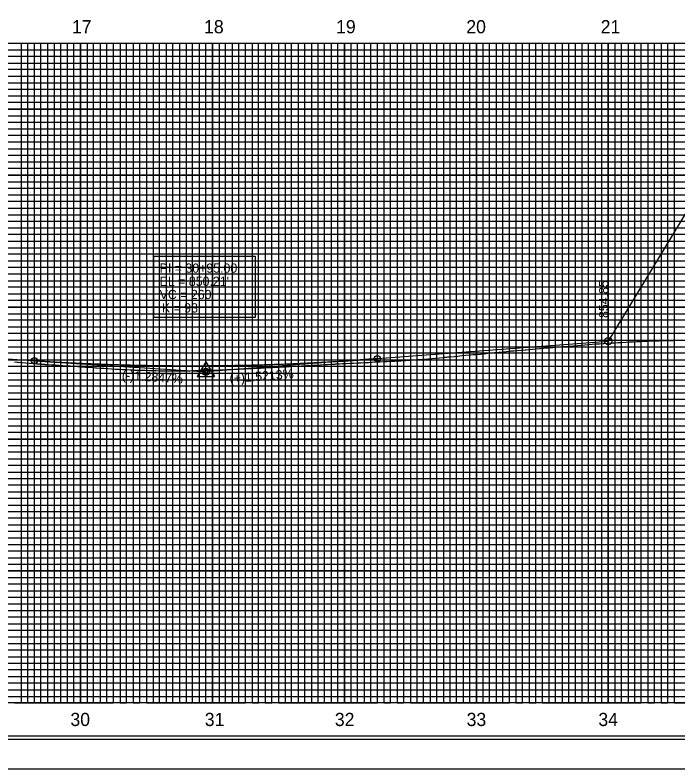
# Model space of a CAD drawing. Extents: x 570622 to 580296, y -55533 to -48575.
# Drawn here: x 571339 to 571841, y -53332 to -52761 of the extents above; entities that cross this region are included whole.
import ezdxf

# ---------------------------------------------------------------- set-up
doc = ezdxf.new("R2010")
doc.units = 0
for name, color, linetype in [('Exist Vertical Profile Ground Line', 7, 'Continuous'), ('Exist Vertical Profile Horizontal Axis Label Major', 7, 'Continuous'), ('Prop Grid Mask', 7, 'Continuous'), ('Prop PFL VPI Symbol CELL', 7, 'Continuous'), ('Prop Vertical Profile Curve Label', 7, 'Continuous'), ('Prop Vertical Profile Grade', 7, 'Continuous'), ('Prop Vertical Profile Grade Label', 7, 'Continuous'), ('Prop VPI Label', 7, 'Continuous'), ('Sheet Cutting Line CELL', 7, 'Continuous'), ('Sheet DOT Grid CELL', 7, 'Continuous'), ('Sheet Layout Profile Border Port 2', 7, 'Continuous'), ('Sheet Plot Border Inside CELL', 7, 'Continuous'), ('Sheet Plot Border Outside CELL', 7, 'Continuous'), ('Sheet Profile CELL', 7, 'Continuous'), ('Sheet Profile Grid Major CELL', 7, 'Continuous'), ('Sheet Profile Grid Middle CELL', 7, 'Continuous'), ('Sheet Profile Grid Minor CELL', 7, 'Continuous')]:
    doc.layers.add(name, color=color, linetype=linetype)

msp = doc.modelspace()

# ---------------------------------------------------------------- linework, layer by layer
at = {"layer": 'Exist Vertical Profile Ground Line'}
for points in [[(571612.65, -53023.63), (571615.47, -53023.49), (571618.3, -53023.35), (571621.12, -53023.22), (571623.95, -53023.08), (571626.77, -53022.94), (571627.94, -53022.89), (571629.59, -53022.8), (571631.75, -53022.68), (571632.42, -53022.64), (571635.24, -53022.44), (571638.07, -53022.25), (571640.89, -53022.06), (571643.92, -53021.86), (571646.54, -53021.64), (571649.36, -53021.39), (571652.18, -53021.15), (571655.01, -53020.9), (571657.83, -53020.66), (571660.66, -53020.42), (571663.48, -53020.18), (571664.39, -53020.11), (571666.3, -53019.93), (571667.15, -53019.85), (571669.13, -53019.66), (571671.95, -53019.38), (571674.77, -53019.11), (571677.6, -53018.84), (571680.42, -53018.58), (571683.25, -53018.31), (571684.39, -53018.2), (571686.07, -53018.08), (571687.71, -53017.95), (571688.89, -53017.86), (571691.72, -53017.63), (571694.54, -53017.35), (571697.37, -53017.07), (571700.19, -53016.79), (571702.41, -53016.57), (571703.01, -53016.51), (571705.84, -53016.23), (571708.66, -53015.95), (571711.48, -53015.66), (571714.31, -53015.38), (571715.13, -53015.3), (571717.13, -53015.14), (571719.96, -53014.91), (571722.78, -53014.69), (571725.6, -53014.46), (571726.16, -53014.42), (571728.43, -53014.2), (571731.25, -53013.93), (571734.07, -53013.65), (571736.9, -53013.38), (571737.36, -53013.34), (571739.72, -53013.15), (571742.55, -53012.92), (571744.07, -53012.8), (571745.37, -53012.69), (571746.82, -53012.57), (571748.19, -53012.47), (571751.02, -53012.24), (571753.84, -53012.02), (571754.58, -53011.96), (571756.67, -53011.79), (571759.49, -53011.56), (571762.31, -53011.33), (571765.14, -53011.09), (571768.15, -53010.85), (571770.78, -53010.64), (571773.61, -53010.43), (571776.43, -53010.21), (571779.26, -53009.99), (571782.08, -53009.78), (571784.9, -53009.56), (571785.37, -53009.52), (571787.73, -53009.39), (571788.76, -53009.32), (571790.55, -53009.23), (571793.37, -53009.08), (571796.2, -53008.93), (571799.02, -53008.79), (571801.85, -53008.64), (571804.67, -53008.49), (571807.49, -53008.35), (571810.32, -53008.2), (571812.56, -53008.08), (571813.14, -53008.05), (571815.97, -53007.88), (571818.04, -53007.76), (571818.79, -53007.74), (571821.83, -53007.67), (571824.44, -53007.61), (571827.26, -53007.54), (571830.08, -53007.47), (571832.91, -53007.4), (571835.73, -53007.33), (571838.56, -53007.26), (571839.93, -53007.23), (571841.38, -53007.2), (571844.2, -53007.14)], [(571338.74, -53023.6), (571341.06, -53023.83), (571341.57, -53023.87), (571344.39, -53024.09), (571347.21, -53024.31), (571350.04, -53024.53), (571352.86, -53024.76), (571355.68, -53024.99), (571357.79, -53025.16), (571358.51, -53025.21), (571361.33, -53025.42), (571361.76, -53025.45), (571364.16, -53025.59), (571366.98, -53025.76), (571369.8, -53025.92), (571372.63, -53026.1), (571375.45, -53026.27), (571378.28, -53026.45), (571380.59, -53026.59), (571381.1, -53026.63), (571383.92, -53026.83)], [(571383.92, -53026.83), (571386.75, -53027.04), (571389.57, -53027.25), (571391.47, -53027.39), (571392.39, -53027.45), (571395.22, -53027.65), (571398.04, -53027.85), (571400.1, -53027.99), (571400.87, -53028.04), (571403.69, -53028.22), (571406.51, -53028.4), (571409.34, -53028.58), (571412.16, -53028.76), (571415.28, -53028.97), (571417.81, -53029.1), (571420.63, -53029.24), (571423.46, -53029.39), (571426.28, -53029.54), (571428.52, -53029.66), (571429.1, -53029.7), (571429.79, -53029.73), (571430.13, -53029.74), (571431.93, -53029.79), (571434.75, -53029.86), (571437.58, -53029.94), (571440.4, -53030.02), (571443.22, -53030.1), (571446.05, -53030.18), (571448.87, -53030.27), (571450.24, -53030.31), (571451.69, -53030.31), (571454.56, -53030.32), (571457.34, -53030.31), (571460.17, -53030.3), (571462.99, -53030.3), (571465.81, -53030.3), (571468.64, -53030.3), (571470.65, -53030.3), (571471.46, -53030.28), (571474.28, -53030.2), (571477.11, -53030.12), (571477.93, -53030.1), (571479.93, -53030.05), (571482.76, -53029.99), (571485.58, -53029.93), (571486.7, -53029.91), (571488.4, -53029.85), (571491.23, -53029.76), (571494.05, -53029.67), (571496.88, -53029.59), (571497.79, -53029.56), (571499.7, -53029.46), (571502.52, -53029.3), (571505.35, -53029.15), (571508.17, -53029.01), (571510.03, -53028.91), (571510.99, -53028.87), (571513.82, -53028.76), (571516.64, -53028.64), (571519.47, -53028.53), (571522.29, -53028.37), (571525.11, -53028.22), (571527.94, -53028.06), (571530.76, -53027.91), (571533.58, -53027.76), (571534.38, -53027.71), (571536.41, -53027.62), (571539.23, -53027.5), (571542.06, -53027.37), (571544.25, -53027.28), (571544.88, -53027.24), (571547.7, -53027.08), (571550.53, -53026.92), (571553.35, -53026.77), (571556.17, -53026.61), (571559, -53026.46), (571560.18, -53026.39), (571561.82, -53026.31), (571563.88, -53026.22), (571564.65, -53026.17), (571567.47, -53026), (571570.29, -53025.84), (571573.12, -53025.67), (571575.94, -53025.51), (571578.77, -53025.35), (571581.59, -53025.19), (571582.13, -53025.16), (571584.41, -53025.04), (571584.99, -53025.01), (571587.24, -53024.9), (571588, -53024.86), (571590.06, -53024.75), (571592.88, -53024.61), (571595.71, -53024.47), (571598.53, -53024.33), (571601.36, -53024.19), (571604.18, -53024.05), (571605.86, -53023.97), (571607, -53023.91), (571609.83, -53023.77), (571612.65, -53023.63)]]:
    msp.add_lwpolyline(points, dxfattribs=at)
at = {"layer": 'Prop Grid Mask'}
msp.add_lwpolyline([(571444.38, -52943.35), (571521.12, -52943.35), (571521.12, -52989.9), (571444.38, -52989.9)], close=True, dxfattribs=at)
at = {"layer": 'Prop PFL VPI Symbol CELL'}
for p, q in [((571483.68, -53023.52), (571477.23, -53034.72)), ((571483.68, -53023.52), (571490.18, -53034.72)), ((571477.23, -53034.72), (571490.18, -53034.72))]:
    msp.add_line(p, q, dxfattribs=at)
for radius in [1.75, 1.2]:
    msp.add_circle((571483.69, -53031), radius, dxfattribs=at)
at = {"layer": 'Prop Vertical Profile Curve Label'}
for centre in [(571613.69, -53021.12), (571353.69, -53022.65)]:
    msp.add_circle(centre, 2.25, dxfattribs=at)
at = {"layer": 'Prop Vertical Profile Grade'}
for p, q in [((571613.69, -53021.12), (571788.69, -53007.8)), ((571298.69, -53019.12), (571355.93, -53022.8))]:
    msp.add_line(p, q, dxfattribs=at)
msp.add_spline([(571353.69, -53022.65), (571358.89, -53022.98), (571364.09, -53023.29), (571369.29, -53023.59), (571374.49, -53023.87), (571379.69, -53024.14), (571384.89, -53024.4), (571390.09, -53024.63), (571395.29, -53024.86), (571400.49, -53025.07), (571405.69, -53025.26), (571410.89, -53025.45), (571416.09, -53025.61), (571421.29, -53025.76), (571426.49, -53025.9), (571431.69, -53026.02), (571436.89, -53026.13), (571442.09, -53026.22), (571447.29, -53026.3), (571452.49, -53026.37), (571457.69, -53026.42), (571462.89, -53026.45), (571468.09, -53026.47), (571473.29, -53026.48), (571478.49, -53026.47), (571483.69, -53026.44), (571488.89, -53026.41), (571494.09, -53026.35), (571499.29, -53026.29), (571504.49, -53026.2), (571509.69, -53026.11), (571514.89, -53026), (571520.09, -53025.87), (571525.29, -53025.73), (571530.49, -53025.58), (571535.69, -53025.41), (571540.89, -53025.22), (571546.09, -53025.03), (571551.29, -53024.81), (571556.49, -53024.58), (571561.69, -53024.34), (571566.89, -53024.08), (571572.09, -53023.81), (571577.29, -53023.53), (571582.49, -53023.23), (571587.69, -53022.91), (571592.89, -53022.58), (571598.09, -53022.24), (571603.29, -53021.88), (571608.49, -53021.5), (571613.69, -53021.12)], degree=3, dxfattribs=at)
at = {"layer": 'Prop VPI Label'}
for p, q in [((571848.68, -52908.54), (571788.69, -53007.8)), ((571353.69, -53022.65), (571480.94, -53030.83)), ((571613.69, -53021.12), (571486.43, -53030.8))]:
    msp.add_line(p, q, dxfattribs=at)
for centre in [(571788.69, -53007.8), (571788.69, -53007.8), (571483.69, -53031), (571483.69, -53031)]:
    msp.add_circle(centre, 2.75, dxfattribs=at)
at = {"layer": 'Sheet Cutting Line CELL'}
msp.add_line((570621.69, -53332.05), (572305.69, -53332.05), dxfattribs=at)
at = {"layer": 'Sheet DOT Grid CELL'}
for p, q in [((570788.69, -52782.05), (572288.57, -52782.05)), ((571388.69, -52782.05), (571388.69, -53282.05)), ((571438.69, -52782.05), (571438.69, -53282.05)), ((571488.69, -52782.05), (571488.69, -53282.05)), ((571538.69, -52782.05), (571538.69, -53282.05)), ((571588.69, -52782.05), (571588.69, -53282.05)), ((571638.69, -52782.05), (571638.69, -53282.05)), ((571688.69, -52782.05), (571688.69, -53282.05)), ((571738.69, -52782.05), (571738.69, -53282.05)), ((571788.69, -52782.05), (571788.69, -53282.05)), ((571838.69, -52782.05), (571838.69, -53282.05)), ((570788.69, -52832.05), (572288.57, -52832.05)), ((570788.69, -52882.05), (572288.57, -52882.05)), ((570788.69, -52932.05), (572288.57, -52932.05)), ((570788.69, -52982.05), (572288.57, -52982.05)), ((570788.69, -53032.05), (572288.57, -53032.05)), ((570788.69, -53082.05), (572288.57, -53082.05)), ((570788.69, -53132.05), (572288.57, -53132.05)), ((570788.69, -53182.05), (572288.57, -53182.05)), ((570788.69, -53232.05), (572288.57, -53232.05))]:
    msp.add_line(p, q, dxfattribs=at)
at = {"layer": 'Sheet Layout Profile Border Port 2'}
msp.add_lwpolyline([(570838.69, -52782.05), (572238.69, -52782.05), (572238.69, -53282.05), (570838.69, -53282.05)], close=True, dxfattribs=at)
at = {"layer": 'Sheet Plot Border Inside CELL'}
msp.add_lwpolyline([(570634.69, -53309.6), (572301.19, -53309.6), (572301.19, -52254.5), (570634.69, -52254.5)], close=True, dxfattribs=at)
at = {"layer": 'Sheet Plot Border Outside CELL'}
msp.add_lwpolyline([(570621.69, -53332.05), (572305.69, -53332.05), (572305.69, -52232.05), (570621.69, -52232.05)], close=True, dxfattribs=at)
at = {"layer": 'Sheet Profile CELL'}
for p, q in [((570788.69, -52782.05), (572288.69, -52782.05)), ((572288.69, -53282.05), (570788.69, -53282.05)), ((570788.69, -53307.05), (572288.69, -53307.05))]:
    msp.add_line(p, q, dxfattribs=at)
msp.add_lwpolyline([(572288.69, -52257.05), (570788.69, -52257.05), (570788.69, -53307.05), (572288.69, -53307.05)], close=True, dxfattribs=at)
at = {"layer": 'Sheet Profile Grid Major CELL'}
for p, q in [((571388.69, -52782.05), (571438.69, -52782.05)), ((571488.69, -52782.05), (571538.69, -52782.05)), ((571588.69, -52782.05), (571638.69, -52782.05)), ((571688.69, -52782.05), (571738.69, -52782.05)), ((571788.69, -52782.05), (571838.69, -52782.05))]:
    msp.add_line(p, q, dxfattribs=at)
for points in [[(571338.69, -53282.05), (571388.69, -53282.05), (571388.69, -52782.05), (571438.69, -52782.05), (571438.69, -53282.05), (571488.69, -53282.05), (571488.69, -52782.05), (571538.69, -52782.05), (571538.69, -53282.05), (571588.69, -53282.05), (571588.69, -52782.05), (571638.69, -52782.05), (571638.69, -53282.05), (571688.69, -53282.05), (571688.69, -52782.05), (571738.69, -52782.05), (571738.69, -53282.05), (571788.69, -53282.05), (571788.69, -52782.05), (571838.69, -52782.05), (571838.69, -53282.05), (571888.69, -53282.05)], [(572288.69, -52832.05), (570788.69, -52832.05)], [(572288.69, -52882.05), (570788.69, -52882.05), (570788.69, -52932.05), (572288.69, -52932.05)], [(572288.69, -52982.05), (570788.69, -52982.05), (570788.69, -53032.05), (572288.69, -53032.05)], [(572288.69, -53082.05), (570788.69, -53082.05), (570788.69, -53132.05), (572288.69, -53132.05)], [(572288.69, -53182.05), (570788.69, -53182.05), (570788.69, -53182.05), (570788.69, -53232.05), (572288.69, -53232.05)], [(572288.69, -53282.05), (570788.69, -53282.05)]]:
    msp.add_lwpolyline(points, dxfattribs=at)
at = {"layer": 'Sheet Profile Grid Middle CELL'}
for points in [[(571313.69, -52782.05), (571363.69, -52782.05), (571363.69, -53282.05), (571413.69, -53282.05), (571413.69, -53282.05), (571413.69, -52782.05), (571463.69, -52782.05), (571463.69, -53282.05), (571513.69, -53282.05), (571513.69, -52782.05), (571563.69, -52782.05), (571563.69, -53282.05), (571613.69, -53282.05), (571613.69, -52782.05), (571663.69, -52782.05), (571663.69, -53282.05), (571713.69, -53282.05), (571713.69, -52782.05), (571763.69, -52782.05), (571763.69, -53282.05), (571813.69, -53282.05), (571813.69, -52782.05), (571863.69, -52782.05)], [(570788.69, -52807.05), (572288.69, -52807.05)], [(572288.69, -52857.05), (570788.69, -52857.05), (570788.69, -52907.05), (572288.69, -52907.05)], [(572288.69, -52957.05), (570788.69, -52957.05), (570788.69, -53007.05), (572288.69, -53007.05)], [(572288.69, -53057.05), (570788.69, -53057.05), (570788.69, -53107.05), (572288.69, -53107.05)], [(572288.69, -53157.05), (570788.69, -53157.05), (570788.69, -53207.05), (572288.69, -53207.05)], [(572288.69, -53257.05), (570788.69, -53257.05)]]:
    msp.add_lwpolyline(points, dxfattribs=at)
at = {"layer": 'Sheet Profile Grid Minor CELL'}
for p, q in [((570838.69, -52787.05), (572238.69, -52787.05)), ((572238.69, -52792.05), (570838.69, -52792.05)), ((570838.69, -52797.05), (572238.69, -52797.05)), ((572238.69, -52802.05), (570838.69, -52802.05)), ((570838.69, -52812.05), (572238.69, -52812.05)), ((572238.69, -52817.05), (570838.69, -52817.05)), ((570838.69, -52822.05), (572238.69, -52822.05)), ((572238.69, -52827.05), (570838.69, -52827.05)), ((570838.69, -52837.05), (572238.69, -52837.05)), ((572238.69, -52842.05), (570838.69, -52842.05)), ((570838.69, -52847.05), (572238.69, -52847.05)), ((572238.69, -52852.05), (570838.69, -52852.05)), ((570838.69, -52862.05), (572238.69, -52862.05)), ((572238.69, -52867.05), (570838.69, -52867.05)), ((570838.69, -52872.05), (572238.69, -52872.05)), ((572238.69, -52877.05), (570838.69, -52877.05)), ((570838.69, -52887.05), (572238.69, -52887.05)), ((572238.69, -52892.05), (570838.69, -52892.05)), ((570838.69, -52897.05), (572238.69, -52897.05)), ((572238.69, -52902.05), (570838.69, -52902.05)), ((570838.69, -52912.05), (572238.69, -52912.05)), ((572238.69, -52917.05), (570838.69, -52917.05)), ((570838.69, -52922.05), (572238.69, -52922.05)), ((572238.69, -52927.05), (570838.69, -52927.05)), ((570838.69, -52937.05), (572238.69, -52937.05)), ((572238.69, -52942.05), (570838.69, -52942.05)), ((570838.69, -52947.05), (572238.69, -52947.05)), ((572238.69, -52952.05), (570838.69, -52952.05)), ((570838.69, -52962.05), (572238.69, -52962.05)), ((572238.69, -52967.05), (570838.69, -52967.05)), ((570838.69, -52972.05), (572238.69, -52972.05)), ((572238.69, -52977.05), (570838.69, -52976.9)), ((570838.69, -52987.05), (572238.69, -52987.05)), ((572238.69, -52992.05), (570838.69, -52992.05)), ((570838.69, -52997.05), (572238.69, -52997.05)), ((572238.69, -53002.05), (570838.69, -53002.05)), ((570838.69, -53012.05), (572238.69, -53012.05)), ((572238.69, -53017.05), (570838.69, -53017.05)), ((570838.69, -53022.05), (572238.69, -53022.05)), ((572238.69, -53027.05), (570838.69, -53027.05)), ((570838.69, -53037.05), (572238.69, -53037.05)), ((572238.69, -53042.05), (570838.69, -53042.05)), ((570838.69, -53047.05), (572238.69, -53047.05)), ((572238.69, -53052.05), (570838.69, -53052.05)), ((570838.69, -53062.05), (572238.69, -53062.05)), ((572238.69, -53067.05), (570838.69, -53067.05)), ((570838.69, -53072.05), (572238.69, -53072.05)), ((572238.69, -53077.05), (570838.69, -53077.05)), ((570838.69, -53087.05), (572238.69, -53087.05)), ((572238.69, -53092.05), (570838.69, -53092.05)), ((570838.69, -53097.05), (572238.69, -53097.05)), ((572238.69, -53102.05), (570838.69, -53102.05)), ((570838.69, -53112.05), (572238.69, -53112.05)), ((572238.69, -53117.05), (570838.69, -53117.05)), ((570838.69, -53122.05), (572238.69, -53122.05)), ((572238.69, -53127.05), (570838.69, -53127.05)), ((570838.69, -53137.05), (572238.69, -53137.05)), ((572238.69, -53142.05), (570838.69, -53142.05)), ((570838.69, -53147.05), (572238.69, -53147.05)), ((572238.69, -53152.05), (570838.69, -53152.05)), ((570838.69, -53162.05), (572238.69, -53162.05)), ((572238.69, -53167.05), (570838.69, -53167.05)), ((570838.69, -53172.05), (572238.69, -53172.05)), ((572238.69, -53177.05), (570838.69, -53177.05)), ((570838.69, -53187.05), (572238.69, -53187.05)), ((572238.69, -53192.05), (570838.69, -53192.05)), ((570838.69, -53197.05), (572238.69, -53197.05)), ((572238.69, -53202.05), (570838.69, -53202.05)), ((570838.69, -53212.05), (572238.69, -53212.05)), ((572238.69, -53217.05), (570838.69, -53217.05)), ((570838.69, -53222.05), (572238.69, -53222.05)), ((572238.69, -53227.05), (570838.69, -53227.05)), ((570838.69, -53237.05), (572238.69, -53237.05)), ((572238.69, -53242.05), (570838.69, -53242.05)), ((570838.69, -53247.05), (572238.69, -53247.05)), ((572238.69, -53252.05), (570838.69, -53252.05)), ((570838.69, -53262.05), (572238.69, -53262.05)), ((572238.69, -53267.05), (570838.69, -53267.05)), ((570838.69, -53272.05), (572238.69, -53272.05)), ((570838.69, -53277.05), (572238.69, -53277.05))]:
    msp.add_line(p, q, dxfattribs=at)
for points in [[(571333.69, -52782.05), (571343.69, -52782.05), (571343.69, -53282.05), (571348.69, -53282.05), (571348.69, -52782.05), (571353.69, -52782.05), (571353.69, -53282.05), (571358.69, -53282.05), (571358.69, -52782.05), (571368.69, -52782.05)], [(571368.69, -52782.05), (571368.69, -53282.05), (571373.69, -53282.05), (571373.69, -52782.05), (571378.69, -52782.05), (571378.69, -53282.05), (571383.69, -53282.05), (571383.69, -52782.05), (571393.69, -52782.05), (571393.69, -53282.05), (571398.69, -53282.05), (571398.69, -52782.05), (571403.69, -52782.05), (571403.69, -53282.05), (571408.69, -53282.05), (571408.69, -52782.05), (571418.69, -52782.05), (571418.69, -53282.05), (571423.69, -53282.05), (571423.69, -52782.05), (571428.69, -52782.05), (571428.69, -53282.05), (571433.69, -53282.05), (571433.69, -52782.05), (571443.69, -52782.05), (571443.69, -53282.05), (571448.69, -53282.05), (571448.69, -52782.05), (571453.69, -52782.05), (571453.69, -53282.05), (571458.69, -53282.05), (571458.69, -52782.05), (571468.69, -52782.05), (571468.69, -53282.05), (571473.69, -53282.05), (571473.69, -52782.05), (571478.69, -52782.05), (571478.69, -53282.05), (571483.69, -53282.05), (571483.69, -52782.05), (571493.69, -52782.05), (571493.69, -53282.05), (571493.69, -53282.05), (571498.69, -53282.05), (571498.69, -52782.05), (571503.69, -52782.05), (571503.69, -53282.05), (571508.69, -53282.05), (571508.69, -52782.05), (571518.69, -52782.05), (571518.69, -53282.05), (571523.69, -53282.05), (571523.69, -52782.05), (571528.69, -52782.05), (571528.69, -53282.05), (571533.69, -53282.05), (571533.69, -52782.05), (571543.69, -52782.05), (571543.69, -53282.05), (571548.69, -53282.05), (571548.69, -52782.05), (571553.69, -52782.05), (571553.69, -53282.05), (571558.69, -53282.05), (571558.69, -52782.05), (571568.69, -52782.05), (571568.69, -53282.05), (571573.69, -53282.05), (571573.69, -52782.05), (571578.69, -52782.05), (571578.69, -53282.05), (571583.69, -53282.05), (571583.69, -52782.05), (571593.69, -52782.05), (571593.69, -53282.05), (571598.69, -53282.05), (571598.69, -52782.05), (571603.69, -52782.05), (571603.69, -53282.05), (571608.69, -53282.05), (571608.69, -52782.05), (571618.69, -52782.05), (571618.69, -53282.05), (571623.69, -53282.05), (571623.69, -52782.05), (571628.69, -52782.05), (571628.69, -53282.05), (571633.69, -53282.05), (571633.69, -52782.05), (571643.69, -52782.05), (571643.69, -53282.05), (571648.39, -53281.5), (571648.69, -53282.05), (571648.69, -52782.05), (571653.69, -52782.05), (571653.69, -53282.05), (571658.69, -53282.05), (571658.69, -52782.05), (571668.69, -52782.05), (571668.69, -53282.05), (571673.69, -53282.05)], [(571673.69, -53282.05), (571673.69, -52782.05), (571678.69, -52782.05), (571678.69, -53282.05), (571683.69, -53282.05), (571683.69, -52782.05), (571693.69, -52782.05), (571693.69, -53282.05), (571698.69, -53282.05), (571698.69, -52782.05), (571703.69, -52782.05), (571703.69, -53282.05), (571708.69, -53282.05), (571708.69, -52782.05), (571718.69, -52782.05), (571718.69, -53282.05), (571723.69, -53282.05), (571723.69, -52782.05), (571728.69, -52782.05), (571728.69, -53282.05), (571733.69, -53282.05), (571733.69, -52782.05), (571743.69, -52782.05), (571743.69, -53282.05), (571748.69, -53282.05), (571748.69, -52782.05), (571753.69, -52782.05), (571753.69, -53282.05), (571758.69, -53282.05), (571758.69, -52782.05), (571768.69, -52782.05), (571768.69, -53282.05), (571773.69, -53282.05), (571773.69, -52782.05), (571778.69, -52782.05), (571778.69, -53282.05), (571783.69, -53282.05), (571783.69, -52782.05), (571793.69, -52782.05), (571793.69, -53282.05), (571798.69, -53282.05), (571798.69, -52782.05), (571803.69, -52782.05), (571803.69, -53282.05), (571808.69, -53282.05), (571808.69, -52782.05), (571818.69, -52782.05), (571818.69, -53282.05), (571823.69, -53282.05), (571823.69, -52782.05), (571828.69, -52782.05), (571828.69, -53282.05), (571833.69, -53282.05), (571833.69, -52782.05), (571843.69, -52782.05)]]:
    msp.add_lwpolyline(points, dxfattribs=at)

# ---------------------------------------------------------------- texts
at = {"layer": 'Exist Vertical Profile Horizontal Axis Label Major'}
for s, p in [('17', (571382.23, -52774.55)), ('18', (571482.35, -52774.55)), ('19', (571582.4, -52774.55)), ('20', (571681.07, -52774.55)), ('21', (571782.91, -52774.55)), ('30', (571381.07, -53299.55)), ('31', (571482.91, -53299.55)), ('32', (571581.46, -53299.55)), ('33', (571681.3, -53299.55)), ('34', (571781.14, -53299.55))]:
    msp.add_text(s, height=10, dxfattribs=at).set_placement(p)
at = {"layer": 'Prop Vertical Profile Curve Label'}
for s, p in [("VC = 260'", (571448.69, -52976)), ('K = 93', (571450.41, -52986.14))]:
    msp.add_text(s, height=7, dxfattribs=at).set_placement(p)
at = {"layer": 'Prop Vertical Profile Grade Label'}
for s, rotation, p in [('(-)1.2847%', 356.3245, (571419.92, -53036.93)), ('(+)1.5213%', 4.3499, (571501.91, -53039.65))]:
    msp.add_text(s, height=7, rotation=rotation, dxfattribs=at).set_placement(p)
at = {"layer": 'Prop VPI Label'}
for s, p in [('PI = 30+95.00', (571448.69, -52956)), ("EL = 850.21'", (571448.69, -52966))]:
    msp.add_text(s, height=7, dxfattribs=at).set_placement(p)
msp.add_text('854.85', height=7, rotation=90, dxfattribs=at).set_placement((571788.69, -52990.3))

doc.saveas('drawing.dxf')
